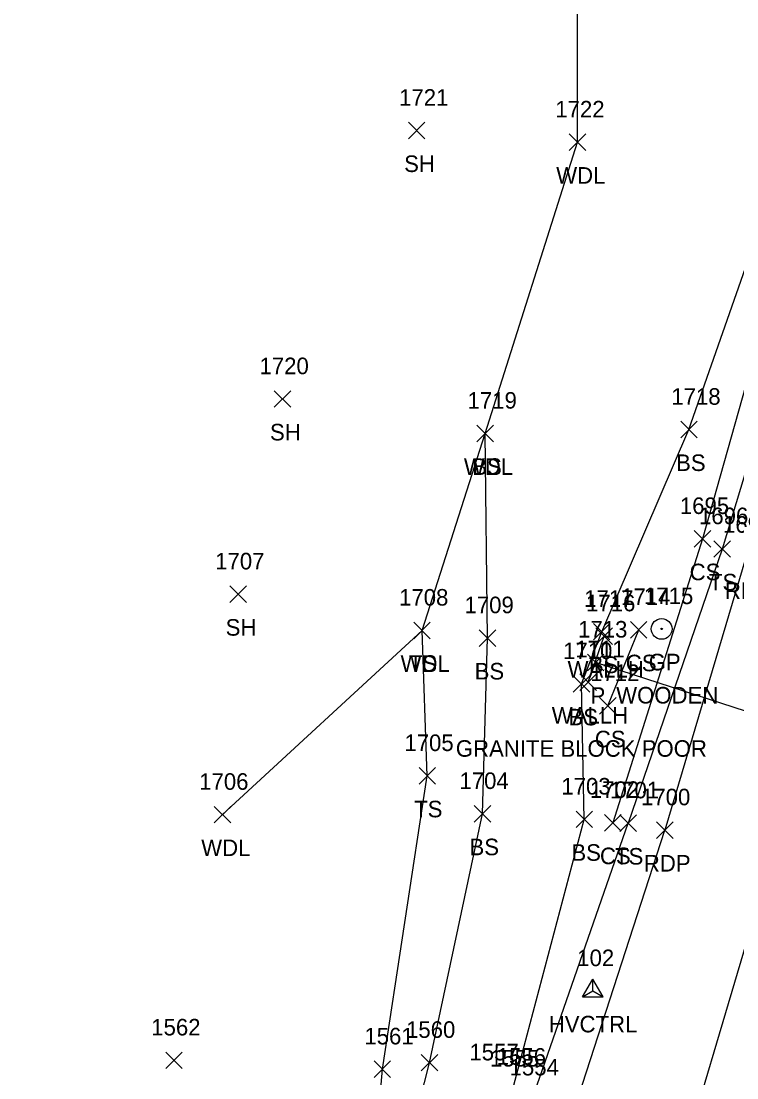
# Model space of a CAD drawing. Extents: x 1654425 to 1656893, y 667839 to 678429.
# Drawn here: x 1654581.9 to 1654668.3, y 668618 to 668745.6 of the extents above; entities that cross this region are included whole.
import ezdxf

# ---------------------------------------------------------------- set-up
doc = ezdxf.new("R2010")
doc.units = 0
for name, color, linetype in [('C_A', 7, 'Continuous'), ('C_I', 7, 'Continuous'), ('CPSM', 7, 'Continuous'), ('D_A', 7, 'Continuous'), ('D_C', 7, 'Continuous'), ('D_I', 7, 'Continuous'), ('D_TIC', 7, 'Continuous'), ('DCP', 7, 'Continuous'), ('DHW', 7, 'Continuous'), ('L_A', 7, 'Continuous'), ('L_I', 7, 'Continuous'), ('L_TIC', 7, 'Continuous'), ('LAWA', 7, 'Continuous'), ('LELB', 7, 'Continuous'), ('P_A', 7, 'Continuous'), ('P_I', 7, 'Continuous'), ('P_TIC', 7, 'Continuous'), ('PET', 7, 'Continuous'), ('PRC', 7, 'Continuous'), ('R_A', 7, 'Continuous'), ('R_C', 7, 'Continuous'), ('R_I', 7, 'Continuous'), ('RGP', 7, 'Continuous'), ('S_I', 7, 'Continuous')]:
    doc.layers.add(name, color=color, linetype=linetype)

msp = doc.modelspace()

# ---------------------------------------------------------------- linework, layer by layer
at = {"layer": 'CPSM'}
for p, q in [((1654649.64, 668627.79), (1654650.89, 668629.95)), ((1654652.14, 668627.79), (1654650.89, 668629.95)), ((1654650.89, 668628.51), (1654650.89, 668629.95)), ((1654649.64, 668627.79), (1654650.89, 668628.51)), ((1654650.89, 668628.51), (1654650.89, 668628.51)), ((1654650.89, 668628.51), (1654652.14, 668627.79)), ((1654649.64, 668627.79), (1654652.14, 668627.79))]:
    msp.add_line(p, q, dxfattribs=at)
at = {"layer": 'D_TIC'}
for points in [[(1654651.26, 668670.35), (1654653.26, 668672.35)], [(1654653.26, 668670.35), (1654651.26, 668672.35)], [(1654650.24, 668667.18), (1654652.24, 668669.18)], [(1654652.24, 668667.18), (1654650.24, 668669.18)], [(1654649.35, 668664.79), (1654651.35, 668666.79)], [(1654651.35, 668664.79), (1654649.35, 668666.79)]]:
    msp.add_lwpolyline(points, dxfattribs=at)
at = {"layer": 'DCP'}
msp.add_lwpolyline([(1654698.21, 668652.91), (1654651.24, 668668.18)], dxfattribs=at)
at = {"layer": 'DHW'}
msp.add_lwpolyline([(1654650.35, 668665.79), (1654652.26, 668671.35)], dxfattribs=at)
at = {"layer": 'L_TIC'}
for points in [[(1654628.63, 668731.39), (1654630.63, 668733.39)], [(1654630.63, 668731.39), (1654628.63, 668733.39)], [(1654648.06, 668729.98), (1654650.06, 668731.98)], [(1654650.06, 668729.98), (1654648.06, 668731.98)], [(1654612.44, 668698.98), (1654614.44, 668700.98)], [(1654614.44, 668698.98), (1654612.44, 668700.98)], [(1654661.51, 668695.29), (1654663.51, 668697.29)], [(1654663.51, 668695.29), (1654661.51, 668697.29)], [(1654636.91, 668694.82), (1654638.91, 668696.82)], [(1654638.91, 668694.82), (1654636.91, 668696.82)], [(1654636.91, 668694.82), (1654638.91, 668696.82)], [(1654638.91, 668694.82), (1654636.91, 668696.82)], [(1654663.15, 668682.1), (1654665.15, 668684.1)], [(1654665.15, 668682.1), (1654663.15, 668684.1)], [(1654665.51, 668680.87), (1654667.51, 668682.87)], [(1654667.51, 668680.87), (1654665.51, 668682.87)], [(1654607.08, 668675.41), (1654609.08, 668677.41)], [(1654609.08, 668675.41), (1654607.08, 668677.41)], [(1654655.44, 668671.11), (1654657.44, 668673.11)], [(1654657.44, 668671.11), (1654655.44, 668673.11)], [(1654629.28, 668671.04), (1654631.28, 668673.04)], [(1654631.28, 668671.04), (1654629.28, 668673.04)], [(1654629.28, 668671.04), (1654631.28, 668673.04)], [(1654631.28, 668671.04), (1654629.28, 668673.04)], [(1654637.19, 668670.12), (1654639.19, 668672.12)], [(1654639.19, 668670.12), (1654637.19, 668672.12)], [(1654650.97, 668670.89), (1654652.97, 668672.89)], [(1654652.97, 668670.89), (1654650.97, 668672.89)], [(1654648.52, 668664.58), (1654650.52, 668666.58)], [(1654650.52, 668664.58), (1654648.52, 668666.58)], [(1654651.7, 668661.93), (1654653.7, 668663.93)], [(1654653.7, 668661.93), (1654651.7, 668663.93)], [(1654629.92, 668653.48), (1654631.92, 668655.48)], [(1654631.92, 668653.48), (1654629.92, 668655.48)], [(1654605.2, 668648.8), (1654607.2, 668650.8)], [(1654607.2, 668648.8), (1654605.2, 668650.8)], [(1654636.57, 668648.9), (1654638.57, 668650.9)], [(1654638.57, 668648.9), (1654636.57, 668650.9)], [(1654648.87, 668648.23), (1654650.87, 668650.23)], [(1654650.87, 668648.23), (1654648.87, 668650.23)], [(1654652.32, 668647.82), (1654654.32, 668649.82)], [(1654654.32, 668647.82), (1654652.32, 668649.82)], [(1654654.17, 668647.77), (1654656.17, 668649.77)], [(1654656.17, 668647.77), (1654654.17, 668649.77)], [(1654654.17, 668647.77), (1654656.17, 668649.77)], [(1654656.17, 668647.77), (1654654.17, 668649.77)], [(1654599.33, 668619.14), (1654601.33, 668621.14)], [(1654601.33, 668619.14), (1654599.33, 668621.14)], [(1654630.18, 668618.85), (1654632.18, 668620.85)], [(1654632.18, 668618.85), (1654630.18, 668620.85)], [(1654624.49, 668618.06), (1654626.49, 668620.06)], [(1654626.49, 668618.06), (1654624.49, 668620.06)]]:
    msp.add_lwpolyline(points, dxfattribs=at)
at = {"layer": 'LAWA'}
msp.add_lwpolyline([(1654606.2, 668649.8), (1654630.28, 668672.04), (1654637.91, 668695.82), (1654649.06, 668730.98), (1654649.01, 668774.26), (1654663.1, 668814.33), (1654677.09, 668857.8), (1654702.3, 668887.53)], dxfattribs=at)
at = {"layer": 'LELB'}
for points in [[(1654581.88, 668581.9), (1654606.98, 668576.45), (1654627.8, 668578.91), (1654641.17, 668616.39), (1654649.87, 668649.23), (1654649.52, 668665.58), (1654651.97, 668671.89), (1654662.51, 668696.29), (1654672.37, 668724.45), (1654685.62, 668761.8), (1654697.84, 668800.3), (1654711.19, 668841.94), (1654722.77, 668879.71)], [(1654727.34, 668878.17), (1654715.11, 668842.6), (1654700.71, 668798.51), (1654686.43, 668755.34), (1654674.1, 668718.36), (1654664.15, 668683.1), (1654653.32, 668648.82)], [(1654730.44, 668877.26), (1654718.47, 668840.65), (1654704.15, 668797.51), (1654690.11, 668753.49), (1654677.29, 668717.55), (1654666.51, 668681.87), (1654655.17, 668648.77)], [(1654622.64, 668586.29), (1654631.18, 668619.85), (1654637.57, 668649.9), (1654638.19, 668671.12), (1654637.91, 668695.82)], [(1654622.64, 668586.29), (1654625.49, 668619.06), (1654630.92, 668654.48), (1654630.28, 668672.04)], [(1654652.7, 668662.93), (1654656.44, 668672.11)], [(1654581.88, 668581.9), (1654607.43, 668571.66), (1654629.53, 668576.46), (1654643.54, 668615.31), (1654655.17, 668648.77)]]:
    msp.add_lwpolyline(points, dxfattribs=at)
at = {"layer": 'P_TIC'}
for points in [[(1654658.58, 668646.93), (1654660.58, 668648.93)], [(1654660.58, 668646.93), (1654658.58, 668648.93)], [(1654658.58, 668646.93), (1654660.58, 668648.93)], [(1654660.58, 668646.93), (1654658.58, 668648.93)]]:
    msp.add_lwpolyline(points, dxfattribs=at)
at = {"layer": 'PET'}
for points in [[(1654734.29, 668876.05), (1654722, 668839.15), (1654707.71, 668796.62), (1654693.12, 668752.48), (1654680.64, 668716.77), (1654669.36, 668680.84), (1654659.58, 668647.93)], [(1654621.12, 668380.08), (1654605.24, 668384.01), (1654589.51, 668387.16), (1654598.99, 668428.03), (1654608.32, 668463.46), (1654620, 668509.52), (1654636.49, 668573.63), (1654648.24, 668612.9), (1654659.58, 668647.93)]]:
    msp.add_lwpolyline(points, dxfattribs=at)
at = {"layer": 'PRC'}
msp.add_lwpolyline([(1654605.24, 668384.01), (1654612.68, 668416.68), (1654623.19, 668461.23), (1654632.58, 668500.46), (1654641.79, 668536.76), (1654650.75, 668570.78), (1654657.62, 668594.43), (1654672.71, 668645.31)], dxfattribs=at)
at = {"layer": 'RGP'}
msp.add_line((1654659.21, 668672.22), (1654659.21, 668672.22), dxfattribs=at)
for radius in [1.25, 0.0833]:
    msp.add_circle((1654659.21, 668672.22), radius, dxfattribs=at)

# ---------------------------------------------------------------- texts
at = {"layer": 'C_A'}
msp.add_text('HVCTRL', height=2, dxfattribs=at).set_placement((1654645.58, 668623.51))
at = {"layer": 'C_I'}
msp.add_text('102', height=2, dxfattribs=at).set_placement((1654649.02, 668631.51))
at = {"layer": 'D_A'}
for s, p in [('WALLH', (1654647.85, 668666.35)), ('P', (1654650.62, 668663.18)), ('WALLH', (1654645.94, 668660.79))]:
    msp.add_text(s, height=2, dxfattribs=at).set_placement(p)
at = {"layer": 'D_C'}
msp.add_text('GRANITE BLOCK POOR', height=2, dxfattribs=at).set_placement((1654634.36, 668656.79))
at = {"layer": 'D_I'}
for s, p in [('1716', (1654650.08, 668674.35)), ('1713', (1654649.12, 668671.18)), ('1711', (1654648.79, 668668.79))]:
    msp.add_text(s, height=2, dxfattribs=at).set_placement(p)
at = {"layer": 'L_A'}
for s, p in [('SH', (1654628.12, 668727.39)), ('WDL', (1654646.48, 668725.98)), ('SH', (1654611.92, 668694.98)), ('WDL', (1654635.33, 668690.82)), ('BS', (1654636.35, 668690.82)), ('BS', (1654660.95, 668691.29)), ('CS', (1654662.59, 668678.1)), ('TS', (1654664.92, 668676.87)), ('SH', (1654606.57, 668671.41)), ('WDL', (1654627.69, 668667.04)), ('TS', (1654628.69, 668667.04)), ('BS', (1654636.63, 668666.12)), ('BS', (1654650.41, 668666.89)), ('CS', (1654654.88, 668667.11)), ('BS', (1654647.96, 668660.58)), ('CS', (1654651.14, 668657.93)), ('TS', (1654629.33, 668649.48)), ('WDL', (1654603.62, 668644.8)), ('BS', (1654636.01, 668644.9)), ('BS', (1654648.31, 668644.23)), ('CS', (1654651.76, 668643.82)), ('TS', (1654653.58, 668643.77)), ('TS', (1654653.58, 668643.77))]:
    msp.add_text(s, height=2, dxfattribs=at).set_placement(p)
at = {"layer": 'L_I'}
for s, p in [('1721', (1654627.51, 668735.39)), ('1722', (1654646.37, 668733.98)), ('1720', (1654610.66, 668702.98)), ('1718', (1654660.38, 668699.29)), ('1719', (1654635.78, 668698.82)), ('1719', (1654635.78, 668698.82)), ('1695', (1654661.41, 668686.1)), ('1696', (1654663.72, 668684.87)), ('1707', (1654605.31, 668679.41)), ('1708', (1654627.51, 668675.04)), ('1708', (1654627.51, 668675.04)), ('1717', (1654649.85, 668674.89)), ('1714', (1654654.31, 668675.11)), ('1709', (1654635.41, 668674.12)), ('1710', (1654647.31, 668668.58)), ('1712', (1654650.58, 668665.93)), ('1705', (1654628.15, 668657.48)), ('1706', (1654603.38, 668652.8)), ('1704', (1654634.8, 668652.9)), ('1703', (1654647.1, 668652.23)), ('1702', (1654650.55, 668651.82)), ('1701', (1654652.96, 668651.77)), ('1701', (1654652.96, 668651.77)), ('1562', (1654597.59, 668623.14)), ('1560', (1654628.35, 668622.85)), ('1561', (1654623.32, 668622.06)), ('1555', (1654638.48, 668619.39)), ('1554', (1654640.85, 668618.31))]:
    msp.add_text(s, height=2, dxfattribs=at).set_placement(p)
at = {"layer": 'P_A'}
for p in [(1654666.85, 668675.84), (1654657.06, 668642.93), (1654657.06, 668642.93)]:
    msp.add_text('RDP', height=2, dxfattribs=at).set_placement(p)
at = {"layer": 'P_I'}
for s, p in [('1697', (1654666.62, 668683.84)), ('1700', (1654656.72, 668650.93)), ('1700', (1654656.72, 668650.93))]:
    msp.add_text(s, height=2, dxfattribs=at).set_placement(p)
at = {"layer": 'R_A'}
msp.add_text('GP', height=2, dxfattribs=at).set_placement((1654657.64, 668667.22))
at = {"layer": 'R_C'}
msp.add_text('WOODEN', height=2, dxfattribs=at).set_placement((1654653.72, 668663.22))
at = {"layer": 'R_I'}
msp.add_text('1715', height=2, dxfattribs=at).set_placement((1654657.08, 668675.22))
at = {"layer": 'S_I'}
for s, p in [('1557', (1654636, 668620.13)), ('1556', (1654639.3, 668619.61))]:
    msp.add_text(s, height=2, dxfattribs=at).set_placement(p)

doc.saveas('drawing.dxf')
